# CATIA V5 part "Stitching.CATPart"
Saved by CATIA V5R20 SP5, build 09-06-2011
Part number: 113T7112-9
Revision: ---
Description: UPPER_PANEL
Bounding box of the stored display mesh (mm): x 32111.289 to 34579.332, y -23460.076 to -18204.377, z 5736.977 to 6343.917
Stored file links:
  \\A5978449\c$\Users\jvl2147\Documents\ASME Y14.37\PartExamples\Stitching.CATPart
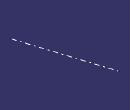
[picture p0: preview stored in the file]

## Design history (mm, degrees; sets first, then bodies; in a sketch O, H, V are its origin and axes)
Set1 "Stitching Definitions:"
  Set2 "Stitching Definition 01"
    DatumCurve1 "Stitch Definition 01"
Body1 "partbody" (main body)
